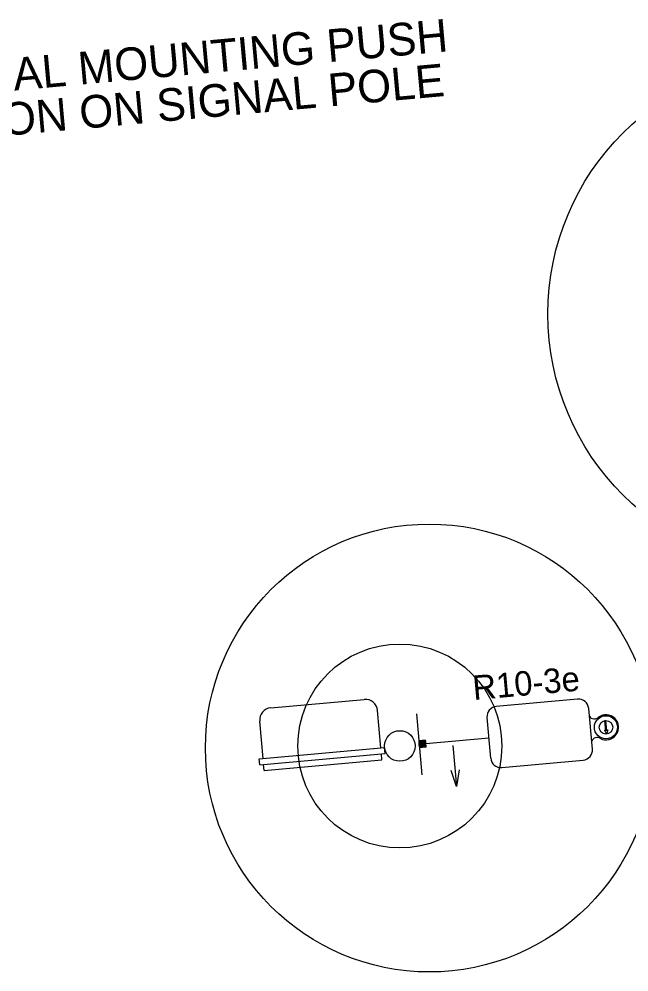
# Model space of a CAD drawing. Extents: x 1277218 to 1279252, y 196860 to 197529.
# Drawn here: x 1279006.3 to 1279120.6, y 197012.4 to 197191 of the extents above; entities that cross this region are included whole.
import ezdxf

# ---------------------------------------------------------------- set-up
doc = ezdxf.new("R2010")
doc.units = 0
doc.layers.add('R_Point Sym', color=7, linetype='Continuous')
doc.layers.add('S_EDGE_PAVEMENT', color=7, linetype='Continuous')

msp = doc.modelspace()

# ---------------------------------------------------------------- linework, layer by layer
at = {"layer": 'S_EDGE_PAVEMENT'}
for p, q in [((1279053.45, 197061.88), (1279070.97, 197063.47)), ((1279110.97, 197063.51), (1279095.71, 197062.13)), ((1279074.09, 197054.41), (1279073.46, 197061.39)), ((1279080.75, 197060.77), (1279081.79, 197049.35)), ((1279113.74, 197054.16), (1279113.05, 197061.78)), ((1279052, 197052.41), (1279051.37, 197059.39)), ((1279093.98, 197060.05), (1279094.67, 197052.43)), ((1279116.06, 197059.48), (1279116.29, 197059.5)), ((1279116.24, 197057.57), (1279116.06, 197059.48)), ((1279116.46, 197057.59), (1279116.29, 197059.5)), ((1279116.03, 197057.71), (1279116.41, 197056.96)), ((1279116.24, 197057.57), (1279116.03, 197057.71)), ((1279116.64, 197057.76), (1279116.41, 197056.96)), ((1279116.64, 197057.76), (1279116.46, 197057.59)), ((1279082.48, 197055.81), (1279081.21, 197055.7)), ((1279081.21, 197055.66), (1279081.25, 197055.7)), ((1279081.21, 197055.68), (1279081.23, 197055.7)), ((1279081.22, 197055.55), (1279081.36, 197055.71)), ((1279081.22, 197055.57), (1279081.33, 197055.71)), ((1279081.22, 197055.59), (1279081.31, 197055.7)), ((1279081.22, 197055.61), (1279081.29, 197055.7)), ((1279081.22, 197055.64), (1279081.27, 197055.7)), ((1279081.23, 197055.44), (1279081.46, 197055.72)), ((1279081.23, 197055.46), (1279081.44, 197055.72)), ((1279081.23, 197055.49), (1279081.42, 197055.71)), ((1279081.23, 197055.51), (1279081.4, 197055.71)), ((1279081.23, 197055.53), (1279081.38, 197055.71)), ((1279081.24, 197055.33), (1279081.57, 197055.73)), ((1279081.24, 197055.36), (1279081.55, 197055.73)), ((1279081.24, 197055.38), (1279081.53, 197055.72)), ((1279081.24, 197055.4), (1279081.51, 197055.72)), ((1279081.24, 197055.42), (1279081.48, 197055.72)), ((1279081.25, 197055.21), (1279081.7, 197055.74)), ((1279081.25, 197055.23), (1279081.68, 197055.74)), ((1279081.25, 197055.25), (1279081.66, 197055.74)), ((1279081.25, 197055.27), (1279081.64, 197055.73)), ((1279081.25, 197055.29), (1279081.61, 197055.73)), ((1279081.25, 197055.31), (1279081.59, 197055.73)), ((1279081.26, 197055.1), (1279081.81, 197055.75)), ((1279081.26, 197055.12), (1279081.79, 197055.75)), ((1279081.26, 197055.14), (1279081.76, 197055.75)), ((1279081.26, 197055.16), (1279081.74, 197055.74)), ((1279081.26, 197055.18), (1279081.72, 197055.74)), ((1279081.27, 197054.99), (1279081.92, 197055.76)), ((1279081.27, 197055.01), (1279081.89, 197055.76)), ((1279081.27, 197055.03), (1279081.87, 197055.76)), ((1279081.27, 197055.05), (1279081.85, 197055.75)), ((1279081.27, 197055.08), (1279081.83, 197055.75)), ((1279081.28, 197054.88), (1279082.02, 197055.77)), ((1279081.28, 197054.9), (1279082, 197055.77)), ((1279081.28, 197054.93), (1279081.98, 197055.76)), ((1279081.28, 197054.95), (1279081.96, 197055.76)), ((1279081.28, 197054.97), (1279081.94, 197055.76)), ((1279081.29, 197054.77), (1279082.13, 197055.78)), ((1279081.29, 197054.8), (1279082.11, 197055.78)), ((1279081.29, 197054.82), (1279082.09, 197055.77)), ((1279081.29, 197054.84), (1279082.07, 197055.77)), ((1279081.29, 197054.86), (1279082.04, 197055.77)), ((1279081.3, 197054.67), (1279082.24, 197055.79)), ((1279081.3, 197054.69), (1279082.22, 197055.79)), ((1279081.3, 197054.71), (1279082.2, 197055.78)), ((1279081.3, 197054.73), (1279082.17, 197055.78)), ((1279081.3, 197054.75), (1279082.15, 197055.78)), ((1279081.31, 197054.56), (1279082.35, 197055.8)), ((1279081.31, 197054.58), (1279082.33, 197055.8)), ((1279081.31, 197054.6), (1279082.3, 197055.79)), ((1279081.31, 197054.62), (1279082.28, 197055.79)), ((1279081.31, 197054.65), (1279082.26, 197055.79)), ((1279081.32, 197054.45), (1279082.45, 197055.81)), ((1279081.32, 197054.47), (1279082.43, 197055.81)), ((1279081.32, 197054.49), (1279082.41, 197055.8)), ((1279081.32, 197054.52), (1279082.39, 197055.8)), ((1279081.32, 197054.54), (1279082.37, 197055.8)), ((1279081.33, 197054.43), (1279082.48, 197055.81)), ((1279081.34, 197054.43), (1279082.48, 197055.79)), ((1279081.36, 197054.43), (1279082.48, 197055.77)), ((1279081.39, 197054.43), (1279082.49, 197055.75)), ((1279081.41, 197054.43), (1279082.49, 197055.73)), ((1279081.43, 197054.43), (1279082.49, 197055.71)), ((1279081.45, 197054.44), (1279082.49, 197055.69)), ((1279081.47, 197054.44), (1279082.49, 197055.66)), ((1279081.49, 197054.44), (1279082.5, 197055.64)), ((1279081.52, 197054.44), (1279082.5, 197055.62)), ((1279081.54, 197054.44), (1279082.5, 197055.6)), ((1279081.56, 197054.45), (1279082.5, 197055.58)), ((1279081.58, 197054.45), (1279082.5, 197055.56)), ((1279081.6, 197054.45), (1279082.51, 197055.53)), ((1279081.62, 197054.45), (1279082.51, 197055.51)), ((1279081.64, 197054.45), (1279082.51, 197055.49)), ((1279081.67, 197054.46), (1279082.51, 197055.47)), ((1279081.69, 197054.46), (1279082.51, 197055.45)), ((1279081.71, 197054.46), (1279082.52, 197055.43)), ((1279081.73, 197054.46), (1279082.52, 197055.41)), ((1279081.75, 197054.46), (1279082.52, 197055.38)), ((1279081.77, 197054.47), (1279082.52, 197055.36)), ((1279081.8, 197054.47), (1279082.52, 197055.34)), ((1279081.82, 197054.47), (1279082.52, 197055.32)), ((1279081.84, 197054.47), (1279082.53, 197055.3)), ((1279081.86, 197054.47), (1279082.53, 197055.28)), ((1279082.6, 197054.54), (1279082.48, 197055.81)), ((1279082.54, 197055.18), (1279094.33, 197056.24)), ((1279051.3, 197052.34), (1279074.79, 197054.47)), ((1279074.9, 197053.33), (1279074.79, 197054.47)), ((1279082.6, 197054.54), (1279081.33, 197054.43)), ((1279081.88, 197054.48), (1279082.53, 197055.25)), ((1279081.9, 197054.48), (1279082.53, 197055.23)), ((1279081.92, 197054.48), (1279082.53, 197055.21)), ((1279081.95, 197054.48), (1279082.54, 197055.19)), ((1279081.97, 197054.48), (1279082.54, 197055.17)), ((1279081.99, 197054.49), (1279082.54, 197055.15)), ((1279082.01, 197054.49), (1279082.54, 197055.12)), ((1279082.03, 197054.49), (1279082.54, 197055.1)), ((1279082.05, 197054.49), (1279082.55, 197055.08)), ((1279082.08, 197054.49), (1279082.55, 197055.06)), ((1279082.1, 197054.5), (1279082.55, 197055.04)), ((1279082.12, 197054.5), (1279082.55, 197055.02)), ((1279082.14, 197054.5), (1279082.55, 197055)), ((1279082.16, 197054.5), (1279082.56, 197054.97)), ((1279082.18, 197054.5), (1279082.56, 197054.95)), ((1279082.2, 197054.5), (1279082.56, 197054.93)), ((1279082.23, 197054.51), (1279082.56, 197054.91)), ((1279082.25, 197054.51), (1279082.56, 197054.89)), ((1279082.27, 197054.51), (1279082.57, 197054.87)), ((1279082.29, 197054.51), (1279082.57, 197054.84)), ((1279082.31, 197054.51), (1279082.57, 197054.82)), ((1279082.33, 197054.52), (1279082.57, 197054.8)), ((1279082.36, 197054.52), (1279082.57, 197054.78)), ((1279082.38, 197054.52), (1279082.58, 197054.76)), ((1279082.4, 197054.52), (1279082.58, 197054.74)), ((1279082.42, 197054.52), (1279082.58, 197054.72)), ((1279082.44, 197054.53), (1279082.58, 197054.69)), ((1279082.46, 197054.53), (1279082.58, 197054.67)), ((1279082.48, 197054.53), (1279082.59, 197054.65)), ((1279082.51, 197054.53), (1279082.59, 197054.63)), ((1279082.53, 197054.53), (1279082.59, 197054.61)), ((1279082.55, 197054.54), (1279082.59, 197054.59)), ((1279082.57, 197054.54), (1279082.59, 197054.56)), ((1279082.59, 197054.54), (1279082.6, 197054.54)), ((1279087.6, 197054.82), (1279088.3, 197047.15)), ((1279051.4, 197051.2), (1279051.3, 197052.34)), ((1279051.4, 197051.2), (1279074.9, 197053.33)), ((1279052.21, 197050.12), (1279074.3, 197052.12)), ((1279074.3, 197052.12), (1279074.2, 197053.27)), ((1279096.75, 197050.7), (1279112.01, 197052.08)), ((1279052.21, 197050.12), (1279052.1, 197051.27))]:
    msp.add_line(p, q, dxfattribs=at)
msp.add_lwpolyline([(1279088.79, 197050.26), (1279088.3, 197047.15), (1279087.26, 197050.13)], dxfattribs=at)
for centre, radius in [((1279153.38, 197135.73), 47.97), ((1279083.18, 197054.35), 41.99), ((1279077.65, 197054.73), 19.12), ((1279116.29, 197058.23), 2.17), ((1279116.29, 197058.23), 1.27), ((1279077.65, 197054.73), 2.87)]:
    msp.add_circle(centre, radius, dxfattribs=at)
for centre, radius, start, end in [((1279071.18, 197061.19), 2.29, 5.1779, 95.1779), ((1279111.15, 197061.61), 1.91, 5.1779, 95.1779), ((1279053.65, 197059.6), 2.29, 95.1779, 185.1779), ((1279095.89, 197060.23), 1.91, 95.1779, 185.1779), ((1279114.11, 197060.86), 1.07, 210.3735, 316.9807), ((1279116.29, 197058.23), 2.36, 243.9181, 126.4377), ((1279116.29, 197058.23), 2.36, 47.6845, 126.4377), ((1279114.62, 197055.26), 1.07, 53.3751, 159.9823), ((1279116.29, 197058.23), 2.36, 243.9181, 322.6712), ((1279111.84, 197053.99), 1.91, 275.1779, 5.1779), ((1279096.58, 197052.61), 1.91, 185.1779, 275.1779)]:
    msp.add_arc(centre, radius, start, end, dxfattribs=at)

# ---------------------------------------------------------------- texts
at = {"layer": 'R_Point Sym'}
for s, p in [('TYPICAL MOUNTING PUSH ', (1278981.35, 197175.43)), ('BUTTON ON SIGNAL POLE ', (1278982.06, 197167.17))]:
    msp.add_text(s, height=6.1199, rotation=5.1779, dxfattribs=at).set_placement(p)
at = {"layer": 'S_EDGE_PAVEMENT'}
msp.add_text('R10-3e', height=4.59, rotation=5.1779, dxfattribs=at).set_placement((1279091.49, 197063.32))

doc.saveas('drawing.dxf')
